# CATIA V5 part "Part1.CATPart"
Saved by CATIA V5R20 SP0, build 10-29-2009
Part number: p11
Bounding box of the stored display mesh (mm): x -5 to 0, y -55 to -45, z 55.01 to 84.991
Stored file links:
  D:\Dropbox\IAO_2011\MMS_GR2\IAO_2011_1439_jlicbarski\Part1.CATPart
  D:\Dropbox\IAO_2011\MMS_GR2\IAO_2011_1439_jlicbarski\train.CATProduct
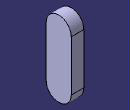
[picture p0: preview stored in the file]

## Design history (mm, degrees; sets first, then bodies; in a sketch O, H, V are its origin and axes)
AxisSystem1: origin (0, 0, 0), X (1, 0, 0), Y (0, 1, 0), Z (0, 0, 1)
Set1
  Plane1: linked copy from another document
  Line1: linked copy from another document
  Line2: linked copy from another document
Body1 (main body)
  Sketch1 on Plane1, origin (0, 0, 0), H (0, 1, 0), V (0, 0, 1)
    arc A1 centre (-50, 80) radius 5 from (-45, 80) to (-54.9999, 80.0254) ccw
    reference projected point E1 (-50, 80) from Line1
    arc A2 centre (-50, 60) radius 5 from (-55, 60.0004) to (-45, 60) ccw
    reference projected point E2 (-50, 60) from Line2
    line L1 (-45, 80) -> (-45, 60)
    line L2 (-54.9999, 80.0254) -> (-55, 60.0004)
    radius A1 = 5
    distance A1 E1 = 5
    radius A2 = 5
    distance A2 E2 = 5
  Pad1: profile Sketch1, direction (-1, 0, 0), length 5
